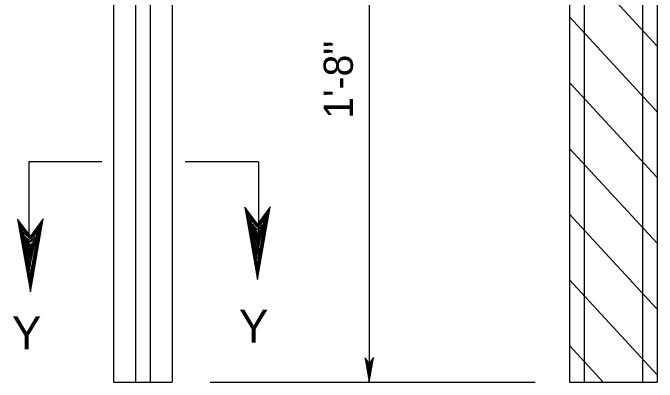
# Model space of a CAD drawing. Extents: x 499866 to 500993, y 499985 to 500645.
# Drawn here: x 500586.4 to 500674.4, y 500052 to 500102.5 of the extents above; entities that cross this region are included whole.
import ezdxf

# ---------------------------------------------------------------- set-up
doc = ezdxf.new("R2010")
doc.units = 0
for name, color, linetype in [('1', 7, 'Continuous'), ('2', 7, 'Continuous'), ('24', 7, 'Continuous'), ('5', 7, 'Continuous'), ('60', 7, 'Continuous')]:
    doc.layers.add(name, color=color, linetype=linetype)

msp = doc.modelspace()

# ---------------------------------------------------------------- linework, layer by layer
at = {"layer": '1'}
for p, q in [((500662.444, 500110.972), (500674.385, 500098.032)), ((500662.444, 500101.98), (500674.385, 500089.039)), ((500662.444, 500092.986), (500674.385, 500080.046)), ((500662.444, 500083.993), (500674.385, 500071.052)), ((500662.444, 500075), (500674.385, 500062.06)), ((500662.444, 500066.007), (500674.385, 500053.066)), ((500662.444, 500057.013), (500667.054, 500052.017))]:
    msp.add_line(p, q, dxfattribs=at)
at = {"layer": '2'}
for p, q in [((500603.117, 500146.946), (500603.117, 500052.017)), ((500605.115, 500146.946), (500605.115, 500052.017)), ((500600.119, 500128.445), (500600.119, 500052.017)), ((500608.113, 500128.405), (500608.113, 500052.017)), ((500588.528, 500082.145), (500588.528, 500067.224)), ((500619.922, 500082.145), (500619.922, 500067.224))]:
    msp.add_line(p, q, dxfattribs=at)
at = {"layer": '24'}
msp.add_lwpolyline([(500635.085, 500052.017), (500635.677, 500055.367), (500635.085, 500054.567), (500634.502, 500055.35), (500635.085, 500052.017), (500635.079, 500052.24), (500635.634, 500055.274), (500635.078, 500054.505), (500634.548, 500055.215), (500635.069, 500052.36), (500635.085, 500052.471), (500635.547, 500055.07), (500635.078, 500054.487), (500634.624, 500055.087), (500635.086, 500052.523), (500635.069, 500052.634), (500635.479, 500054.906), (500635.086, 500054.464), (500634.677, 500054.915), (500635.068, 500052.957), (500635.069, 500053.146), (500635.394, 500054.737), (500635.095, 500054.427), (500634.762, 500054.761), (500635.085, 500053.18), (500635.096, 500053.359), (500635.301, 500054.555), (500635.068, 500054.325), (500634.839, 500054.574), (500635.085, 500053.523), (500635.102, 500053.692), (500635.24, 500054.41), (500635.078, 500054.292), (500634.899, 500054.488), (500635.086, 500053.78), (500635.197, 500054.248), (500635.069, 500054.18), (500634.94, 500054.386), (500635.068, 500053.897), (500635.145, 500054.205), (500635.044, 500054.076), (500634.984, 500054.224), (500635.078, 500054.077), (500635.095, 500054.154)], dxfattribs=at)
at = {"layer": '5'}
for p, q in [((500662.444, 500146.946), (500662.444, 500052.017)), ((500664.442, 500146.946), (500664.442, 500052.017)), ((500672.436, 500146.86), (500672.436, 500052.017)), ((500674.434, 500146.86), (500674.434, 500052.017)), ((500635.085, 500126.95), (500635.085, 500052.017)), ((500598.521, 500082.145), (500588.528, 500082.145)), ((500619.922, 500082.145), (500609.929, 500082.145)), ((500600.119, 500052.017), (500608.113, 500052.017)), ((500613.308, 500052.017), (500657.767, 500052.017))]:
    msp.add_line(p, q, dxfattribs=at)
for points in [[(500619.788, 500066.04), (500621.551, 500076.011), (500619.788, 500073.63), (500618.053, 500075.96), (500619.788, 500066.04), (500619.769, 500066.702), (500621.42, 500075.732), (500619.767, 500073.443), (500618.19, 500075.557), (500619.739, 500067.06), (500619.788, 500067.392), (500621.163, 500075.127), (500619.768, 500073.391), (500618.414, 500075.177), (500619.789, 500067.543), (500619.739, 500067.875), (500620.959, 500074.637), (500619.789, 500073.322), (500618.572, 500074.664), (500619.738, 500068.838), (500619.738, 500069.401), (500620.708, 500074.135), (500619.816, 500073.214), (500618.824, 500074.206), (500619.788, 500069.501), (500619.819, 500070.033), (500620.428, 500073.594), (500619.737, 500072.909), (500619.055, 500073.651), (500619.788, 500070.523), (500619.838, 500071.025), (500620.247, 500073.162), (500619.767, 500072.81), (500619.234, 500073.393), (500619.789, 500071.285), (500620.12, 500072.679), (500619.738, 500072.478), (500619.356, 500073.09), (500619.737, 500071.636), (500619.967, 500072.551), (500619.665, 500072.168), (500619.485, 500072.607), (500619.767, 500072.17), (500619.816, 500072.399)], [(500588.741, 500064.382), (500590.504, 500074.354), (500588.741, 500071.972), (500587.006, 500074.302), (500588.741, 500064.382), (500588.722, 500065.045), (500590.373, 500074.074), (500588.72, 500071.785), (500587.143, 500073.899), (500588.692, 500065.402), (500588.741, 500065.734), (500590.116, 500073.469), (500588.721, 500071.734), (500587.367, 500073.519), (500588.742, 500065.885), (500588.692, 500066.217), (500589.912, 500072.979), (500588.742, 500071.663), (500587.525, 500073.006), (500588.691, 500067.18), (500588.692, 500067.743), (500589.661, 500072.477), (500588.769, 500071.556), (500587.778, 500072.548), (500588.741, 500067.843), (500588.772, 500068.376), (500589.382, 500071.936), (500588.69, 500071.251), (500588.008, 500071.993), (500588.741, 500068.865), (500588.791, 500069.367), (500589.2, 500071.505), (500588.72, 500071.153), (500588.187, 500071.736), (500588.743, 500069.627), (500589.073, 500071.021), (500588.692, 500070.821), (500588.31, 500071.432), (500588.69, 500069.978), (500588.92, 500070.893), (500588.618, 500070.51), (500588.439, 500070.949), (500588.72, 500070.512), (500588.769, 500070.741)]]:
    msp.add_lwpolyline(points, dxfattribs=at)
at = {"layer": '60'}
msp.add_line((500662.444, 500052.017), (500674.434, 500052.017), dxfattribs=at)

# ---------------------------------------------------------------- texts
at = {"layer": '5'}
msp.add_text('1\'-8"', height=4, rotation=90, dxfattribs=at).set_placement((500632.836, 500088.054))
for p in [(500617.269, 500057.418), (500586.223, 500056.514)]:
    msp.add_text('Y', height=4.5, dxfattribs=at).set_placement(p)

doc.saveas('drawing.dxf')
